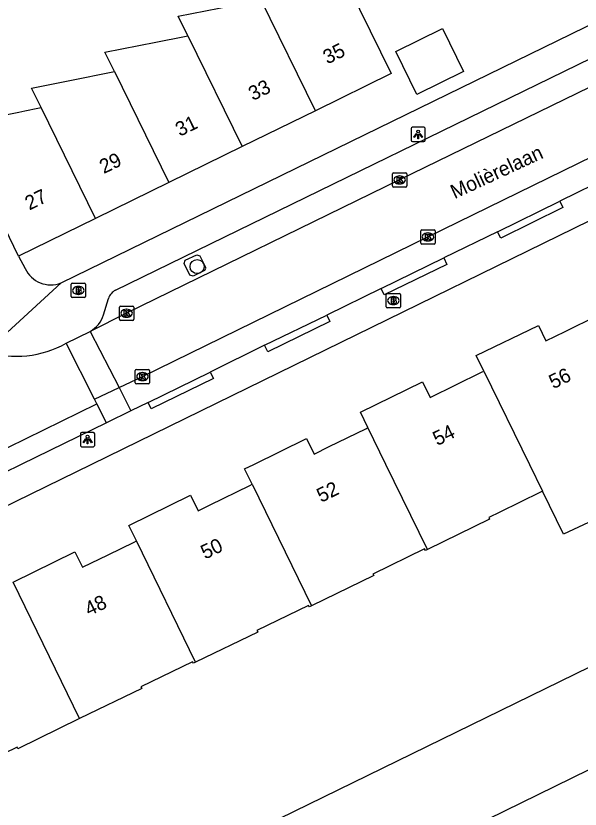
# Model space of a CAD drawing. Extents: x 160457 to 162082, y 388340 to 389736.
# Drawn here: x 160872.8 to 160912.2, y 388725.9 to 388781.3 of the extents above; entities that cross this region are included whole.
import ezdxf

# ---------------------------------------------------------------- set-up
doc = ezdxf.new("R2010")
doc.units = 0
for name, color, linetype in [('IMGEO_Boom', 7, 'Continuous'), ('IMGEO_Brandkraan', 7, 'Continuous'), ('IMGEO_Kolk', 7, 'Continuous'), ('IMGEO_Lichtpunt', 7, 'Continuous'), ('IMGEO_Openbare_ruimte_label', 7, 'Continuous'), ('IMGEO_Pand', 7, 'Continuous'), ('IMGEO_Pand_nummerreeks', 7, 'Continuous'), ('IMGEO_Parkeervlak_open', 7, 'Continuous'), ('IMGEO_Rijbaan_lokaal_gesloten', 7, 'Continuous'), ('IMGEO_Rijbaan_lokaal_open', 7, 'Continuous'), ('IMGEO_Voetpad_open', 7, 'Continuous'), ('IMGEO_Waterloop', 7, 'Continuous')]:
    doc.layers.add(name, color=color, linetype=linetype)

msp = doc.modelspace()

# ---------------------------------------------------------------- linework, layer by layer
at = {"layer": 'IMGEO_Boom'}
msp.add_circle((160885.427, 388763.797), 0.489, dxfattribs=at)
at = {"layer": 'IMGEO_Brandkraan'}
for p, q in [((160876.642, 388761.709), (160876.642, 388762.561)), ((160876.717, 388762.635), (160877.569, 388762.635)), ((160877.643, 388762.561), (160877.643, 388761.709)), ((160877.13, 388762.415), (160877.155, 388762.415)), ((160877.569, 388761.635), (160876.717, 388761.635)), ((160877.153, 388761.855), (160877.128, 388761.855)), ((160898.623, 388761.001), (160898.623, 388761.853)), ((160898.698, 388761.927), (160899.55, 388761.927)), ((160899.111, 388761.707), (160899.136, 388761.707)), ((160899.624, 388761.853), (160899.624, 388761.001)), ((160899.55, 388760.927), (160898.698, 388760.927)), ((160899.134, 388761.147), (160899.109, 388761.147))]:
    msp.add_line(p, q, dxfattribs=at)
for points in [[(160876.642, 388761.709), (160876.642, 388762.561)], [(160876.717, 388762.635), (160877.569, 388762.635)], [(160877.643, 388762.561), (160877.643, 388761.709)], [(160876.99, 388762.335), (160876.99, 388761.935), (160877.203, 388761.935)], [(160877.221, 388762.335), (160876.99, 388762.335)], [(160877.169, 388762.254), (160877.115, 388762.254), (160877.115, 388762.178)], [(160877.115, 388762.178), (160877.168, 388762.178)], [(160877.177, 388762.102), (160877.115, 388762.102), (160877.115, 388762.021)], [(160877.115, 388762.021), (160877.177, 388762.021)], [(160877.569, 388761.635), (160876.717, 388761.635)], [(160898.623, 388761.001), (160898.623, 388761.853)], [(160898.698, 388761.927), (160899.55, 388761.927)], [(160898.971, 388761.627), (160898.971, 388761.227), (160899.184, 388761.227)], [(160899.202, 388761.627), (160898.971, 388761.627)], [(160899.15, 388761.546), (160899.096, 388761.546), (160899.096, 388761.47)], [(160899.096, 388761.47), (160899.149, 388761.47)], [(160899.624, 388761.853), (160899.624, 388761.001)], [(160899.55, 388760.927), (160898.698, 388760.927)], [(160899.158, 388761.394), (160899.096, 388761.394), (160899.096, 388761.313)], [(160899.096, 388761.313), (160899.158, 388761.313)]]:
    msp.add_lwpolyline(points, dxfattribs=at)
for centre, radius, start, end in [((160876.719, 388762.559), 0.0765, 91.552, 178.448), ((160876.719, 388762.559), 0.0765, 91.552, 178.448), ((160877.567, 388762.559), 0.0765, 1.552, 88.448), ((160877.567, 388762.559), 0.0765, 1.552, 88.448), ((160877.17, 388762.216), 0.0379, 267.8285, 90.9355), ((160877.178, 388762.061), 0.0404, 269.8759, 90.5077), ((160877.225, 388762.19), 0.145, 59.4692, 91.5367), ((160877.25, 388762.237), 0.0922, 285.5137, 58.1501), ((160877.255, 388762.045), 0.105, 301.3115, 78.989), ((160876.719, 388761.711), 0.0765, 181.552, 268.448), ((160876.719, 388761.711), 0.0765, 181.552, 268.448), ((160877.209, 388762.186), 0.251, 268.6676, 293.5347), ((160877.567, 388761.711), 0.0765, 271.552, 358.448), ((160877.567, 388761.711), 0.0765, 271.552, 358.448), ((160898.7, 388761.851), 0.0765, 91.552, 178.448), ((160898.7, 388761.851), 0.0765, 91.552, 178.448), ((160899.151, 388761.508), 0.0379, 267.8285, 90.9355), ((160899.206, 388761.482), 0.145, 59.4692, 91.5367), ((160899.231, 388761.529), 0.0922, 285.5137, 58.1501), ((160899.236, 388761.337), 0.105, 301.3115, 78.989), ((160899.548, 388761.851), 0.0765, 1.552, 88.448), ((160899.548, 388761.851), 0.0765, 1.552, 88.448), ((160898.7, 388761.003), 0.0765, 181.552, 268.448), ((160898.7, 388761.003), 0.0765, 181.552, 268.448), ((160899.159, 388761.353), 0.0404, 269.8759, 90.5077), ((160899.19, 388761.478), 0.251, 268.6676, 293.5347), ((160899.548, 388761.003), 0.0765, 271.552, 358.448), ((160899.548, 388761.003), 0.0765, 271.552, 358.448)]:
    msp.add_arc(centre, radius, start, end, dxfattribs=at)
for centre, major_axis, ratio, start_param, end_param in [((160877.129, 388762.135), (-0.387, 0.002), 0.722429, 4.712389, 7.853982), ((160877.154, 388762.135), (-0.39, 0.002), 0.717154, 1.570796, 4.712389), ((160899.11, 388761.427), (-0.387, 0.002), 0.722429, 4.712389, 7.853982), ((160899.135, 388761.427), (-0.39, 0.002), 0.717154, 1.570796, 4.712389)]:
    msp.add_ellipse(centre, major_axis=major_axis, ratio=ratio, start_param=start_param, end_param=end_param, dxfattribs=at)
at = {"layer": 'IMGEO_Kolk'}
for p, q in [((160899.059, 388769.421), (160899.059, 388770.273)), ((160899.134, 388770.347), (160899.986, 388770.347)), ((160900.06, 388770.273), (160900.06, 388769.421)), ((160899.547, 388770.127), (160899.572, 388770.127)), ((160899.986, 388769.347), (160899.134, 388769.347)), ((160899.57, 388769.567), (160899.545, 388769.567)), ((160901.034, 388765.438), (160901.034, 388766.29)), ((160901.109, 388766.364), (160901.961, 388766.364)), ((160901.522, 388766.144), (160901.547, 388766.144)), ((160902.035, 388766.29), (160902.035, 388765.438)), ((160901.961, 388765.364), (160901.109, 388765.364)), ((160901.545, 388765.584), (160901.52, 388765.584)), ((160880.009, 388760.12), (160880.009, 388760.972)), ((160880.084, 388761.046), (160880.936, 388761.046)), ((160881.01, 388760.972), (160881.01, 388760.12)), ((160880.497, 388760.826), (160880.522, 388760.826)), ((160880.936, 388760.046), (160880.084, 388760.046)), ((160880.52, 388760.266), (160880.495, 388760.266)), ((160881.116, 388755.698), (160881.116, 388756.55)), ((160881.191, 388756.624), (160882.043, 388756.624)), ((160882.117, 388756.55), (160882.117, 388755.698)), ((160881.604, 388756.404), (160881.629, 388756.404)), ((160882.043, 388755.624), (160881.191, 388755.624)), ((160881.627, 388755.844), (160881.602, 388755.844))]:
    msp.add_line(p, q, dxfattribs=at)
for points in [[(160899.059, 388769.421), (160899.059, 388770.273)], [(160899.134, 388770.347), (160899.986, 388770.347)], [(160900.06, 388770.273), (160900.06, 388769.421)], [(160899.38, 388770.047), (160899.503, 388770.047), (160899.503, 388769.896), (160899.633, 388770.047), (160899.797, 388770.047), (160899.651, 388769.896), (160899.804, 388769.647), (160899.652, 388769.647), (160899.567, 388769.811), (160899.503, 388769.744), (160899.503, 388769.647), (160899.38, 388769.647), (160899.38, 388770.047)], [(160899.986, 388769.347), (160899.134, 388769.347)], [(160901.034, 388765.438), (160901.034, 388766.29)], [(160901.109, 388766.364), (160901.961, 388766.364)], [(160901.355, 388766.064), (160901.478, 388766.064), (160901.478, 388765.913), (160901.608, 388766.064), (160901.772, 388766.064), (160901.626, 388765.913), (160901.779, 388765.664), (160901.627, 388765.664), (160901.542, 388765.828), (160901.478, 388765.761), (160901.478, 388765.664), (160901.355, 388765.664), (160901.355, 388766.064)], [(160902.035, 388766.29), (160902.035, 388765.438)], [(160901.961, 388765.364), (160901.109, 388765.364)], [(160880.009, 388760.12), (160880.009, 388760.972)], [(160880.084, 388761.046), (160880.936, 388761.046)], [(160881.01, 388760.972), (160881.01, 388760.12)], [(160880.33, 388760.746), (160880.453, 388760.746), (160880.453, 388760.595), (160880.583, 388760.746), (160880.747, 388760.746), (160880.601, 388760.595), (160880.754, 388760.346), (160880.602, 388760.346), (160880.517, 388760.51), (160880.453, 388760.443), (160880.453, 388760.346), (160880.33, 388760.346), (160880.33, 388760.746)], [(160880.936, 388760.046), (160880.084, 388760.046)], [(160881.116, 388755.698), (160881.116, 388756.55)], [(160881.191, 388756.624), (160882.043, 388756.624)], [(160882.117, 388756.55), (160882.117, 388755.698)], [(160881.437, 388756.324), (160881.56, 388756.324), (160881.56, 388756.173), (160881.69, 388756.324), (160881.854, 388756.324), (160881.708, 388756.173), (160881.861, 388755.924), (160881.709, 388755.924), (160881.624, 388756.088), (160881.56, 388756.021), (160881.56, 388755.924), (160881.437, 388755.924), (160881.437, 388756.324)], [(160882.043, 388755.624), (160881.191, 388755.624)]]:
    msp.add_lwpolyline(points, dxfattribs=at)
for centre, start, end in [((160899.136, 388770.271), 91.552, 178.448), ((160899.136, 388770.271), 91.552, 178.448), ((160899.984, 388770.271), 1.552, 88.448), ((160899.984, 388770.271), 1.552, 88.448), ((160899.136, 388769.423), 181.552, 268.448), ((160899.136, 388769.423), 181.552, 268.448), ((160899.984, 388769.423), 271.552, 358.448), ((160899.984, 388769.423), 271.552, 358.448), ((160901.111, 388766.288), 91.552, 178.448), ((160901.111, 388766.288), 91.552, 178.448), ((160901.959, 388766.288), 1.552, 88.448), ((160901.959, 388766.288), 1.552, 88.448), ((160901.111, 388765.44), 181.552, 268.448), ((160901.111, 388765.44), 181.552, 268.448), ((160901.959, 388765.44), 271.552, 358.448), ((160901.959, 388765.44), 271.552, 358.448), ((160880.086, 388760.97), 91.552, 178.448), ((160880.086, 388760.97), 91.552, 178.448), ((160880.934, 388760.97), 1.552, 88.448), ((160880.934, 388760.97), 1.552, 88.448), ((160880.086, 388760.122), 181.552, 268.448), ((160880.086, 388760.122), 181.552, 268.448), ((160880.934, 388760.122), 271.552, 358.448), ((160880.934, 388760.122), 271.552, 358.448), ((160881.193, 388756.548), 91.552, 178.448), ((160881.193, 388756.548), 91.552, 178.448), ((160882.041, 388756.548), 1.552, 88.448), ((160882.041, 388756.548), 1.552, 88.448), ((160881.193, 388755.7), 181.552, 268.448), ((160881.193, 388755.7), 181.552, 268.448), ((160882.041, 388755.7), 271.552, 358.448), ((160882.041, 388755.7), 271.552, 358.448)]:
    msp.add_arc(centre, 0.0765, start, end, dxfattribs=at)
for centre, major_axis, ratio, start_param, end_param in [((160899.546, 388769.847), (-0.387, 0.002), 0.722429, 4.712389, 7.853982), ((160899.571, 388769.847), (-0.39, 0.002), 0.717154, 1.570796, 4.712389), ((160901.521, 388765.864), (-0.387, 0.002), 0.722429, 4.712389, 7.853982), ((160901.546, 388765.864), (-0.39, 0.002), 0.717154, 1.570796, 4.712389), ((160880.496, 388760.546), (-0.387, 0.002), 0.722429, 4.712389, 7.853982), ((160880.521, 388760.546), (-0.39, 0.002), 0.717154, 1.570796, 4.712389), ((160881.603, 388756.124), (-0.387, 0.002), 0.722429, 4.712389, 7.853982), ((160881.628, 388756.124), (-0.39, 0.002), 0.717154, 1.570796, 4.712389)]:
    msp.add_ellipse(centre, major_axis=major_axis, ratio=ratio, start_param=start_param, end_param=end_param, dxfattribs=at)
at = {"layer": 'IMGEO_Lichtpunt'}
for p, q in [((160900.355, 388773.421), (160900.355, 388772.614)), ((160900.355, 388773.421), (160900.355, 388772.614)), ((160901.257, 388773.516), (160900.449, 388773.516)), ((160901.257, 388773.516), (160900.449, 388773.516)), ((160901.351, 388772.614), (160901.351, 388773.421)), ((160901.351, 388772.614), (160901.351, 388773.421)), ((160900.449, 388772.52), (160901.257, 388772.52)), ((160900.449, 388772.52), (160901.257, 388772.52)), ((160877.289, 388752.135), (160877.289, 388751.328)), ((160877.289, 388752.135), (160877.289, 388751.328)), ((160878.191, 388752.23), (160877.383, 388752.23)), ((160878.191, 388752.23), (160877.383, 388752.23)), ((160878.285, 388751.328), (160878.285, 388752.135)), ((160878.285, 388751.328), (160878.285, 388752.135)), ((160877.383, 388751.234), (160878.191, 388751.234)), ((160877.383, 388751.234), (160878.191, 388751.234))]:
    msp.add_line(p, q, dxfattribs=at)
for points in [[(160900.729, 388773.085), (160900.768, 388773.057), (160900.58, 388772.795), (160900.542, 388772.822), (160900.729, 388773.085)], [(160900.831, 388773.037), (160900.878, 388773.037), (160900.878, 388772.715), (160900.831, 388772.715), (160900.831, 388773.037)], [(160900.941, 388773.057), (160900.979, 388773.084), (160901.166, 388772.822), (160901.127, 388772.794), (160900.941, 388773.057)], [(160877.663, 388751.799), (160877.702, 388751.771), (160877.514, 388751.509), (160877.476, 388751.536), (160877.663, 388751.799)], [(160877.765, 388751.751), (160877.812, 388751.751), (160877.812, 388751.429), (160877.765, 388751.429), (160877.765, 388751.751)], [(160877.875, 388751.771), (160877.913, 388751.798), (160878.1, 388751.536), (160878.061, 388751.508), (160877.875, 388751.771)]]:
    msp.add_lwpolyline(points, dxfattribs=at)
for centre in [(160900.854, 388773.219), (160877.788, 388751.933)]:
    msp.add_circle(centre, 0.0994, dxfattribs=at)
for centre, start, end in [((160900.449, 388773.421), 90, 180), ((160900.449, 388773.421), 90, 180), ((160901.257, 388773.421), 0, 90), ((160901.257, 388773.421), 0, 90), ((160900.449, 388772.614), 180, 270), ((160900.449, 388772.614), 180, 270), ((160901.257, 388772.614), 270, 0), ((160901.257, 388772.614), 270, 360), ((160877.383, 388752.135), 90, 180), ((160877.383, 388752.135), 90, 180), ((160878.191, 388752.135), 0, 90), ((160878.191, 388752.135), 0, 90), ((160877.383, 388751.328), 180, 270), ((160877.383, 388751.328), 180, 270), ((160878.191, 388751.328), 270, 0), ((160878.191, 388751.328), 270, 360)]:
    msp.add_arc(centre, 0.0946, start, end, dxfattribs=at)
at = {"layer": 'IMGEO_Pand'}
for points in [[(160889.897, 388782.413), (160889.234, 388783.768), (160889.07, 388784.103), (160894.367, 388786.694), (160895.228, 388784.923), (160896.769, 388781.756), (160898.969, 388777.266), (160893.681, 388774.675)], [(160884.78, 388779.906), (160884.117, 388781.262), (160887.932, 388782.021), (160889.672, 388782.368), (160889.897, 388782.413)], [(160893.681, 388774.675), (160889.897, 388782.413)], [(160899.294, 388778.812), (160902.551, 388780.407), (160904.026, 388777.398), (160900.769, 388775.802), (160899.294, 388778.812)], [(160879.663, 388777.399), (160879, 388778.755), (160882.554, 388779.462), (160884.555, 388779.861), (160884.78, 388779.906)], [(160884.78, 388779.906), (160888.563, 388772.168)], [(160874.546, 388774.892), (160873.883, 388776.248), (160876.661, 388776.801), (160879.438, 388777.354), (160879.663, 388777.399)], [(160879.663, 388777.399), (160883.446, 388769.66)], [(160868.516, 388773.685), (160872.989, 388774.58), (160873.419, 388774.666), (160874.321, 388774.847), (160874.546, 388774.892)], [(160878.329, 388767.153), (160874.546, 388774.892)], [(160893.681, 388774.675), (160888.563, 388772.168)], [(160872.977, 388764.531), (160868.516, 388773.685)], [(160888.563, 388772.168), (160883.446, 388769.66)], [(160883.446, 388769.66), (160878.329, 388767.153)], [(160878.329, 388767.153), (160872.977, 388764.531)], [(160905.432, 388756.511), (160904.905, 388757.589), (160909.244, 388759.7), (160909.769, 388758.621), (160911.113, 388759.28), (160913.365, 388760.383), (160913.506, 388760.452)], [(160897.351, 388752.562), (160896.824, 388753.641), (160901.153, 388755.751), (160901.679, 388754.672), (160903.479, 388755.554), (160905.278, 388756.436), (160905.432, 388756.511)], [(160905.432, 388756.511), (160908.615, 388750), (160909.532, 388748.124)], [(160889.269, 388748.608), (160888.742, 388749.687), (160889.385, 388750), (160893.068, 388751.796), (160893.594, 388750.717), (160894.654, 388751.238), (160897.195, 388752.486), (160897.351, 388752.562)], [(160901.5, 388744.065), (160898.602, 388750), (160897.351, 388752.562)], [(160917.66, 388751.963), (160917.512, 388751.891), (160917.46, 388751.998), (160916.111, 388751.339), (160916.803, 388750), (160917.703, 388748.259), (160910.996, 388745.13), (160909.532, 388748.124)], [(160881.194, 388744.662), (160880.669, 388745.741), (160884.978, 388747.842), (160885.505, 388746.764), (160886.34, 388747.173), (160889.113, 388748.532), (160889.269, 388748.608)], [(160889.269, 388748.608), (160893.408, 388740.129)], [(160909.532, 388748.124), (160909.385, 388748.052), (160906.545, 388746.665), (160905.775, 388746.288), (160905.828, 388746.18), (160901.5, 388744.065)], [(160872.599, 388741.787), (160876.898, 388743.896), (160877.427, 388742.819), (160879.228, 388743.7), (160881.029, 388744.581), (160881.194, 388744.662)], [(160885.316, 388736.194), (160881.194, 388744.662)], [(160901.5, 388744.065), (160901.355, 388743.994), (160901.303, 388744.102), (160897.696, 388742.348), (160897.749, 388742.24), (160893.408, 388740.129)], [(160877.233, 388732.263), (160872.599, 388741.787)], [(160893.408, 388740.129), (160893.261, 388740.058), (160893.209, 388740.166), (160889.603, 388738.412), (160889.655, 388738.304), (160885.316, 388736.194)], [(160885.316, 388736.194), (160885.168, 388736.122), (160885.115, 388736.23), (160881.509, 388734.476), (160881.562, 388734.368), (160877.233, 388732.263)], [(160877.233, 388732.263), (160872.919, 388730.166), (160872.867, 388730.274), (160869.261, 388728.52), (160869.313, 388728.412), (160869.159, 388728.337)]]:
    msp.add_lwpolyline(points, dxfattribs=at)
at = {"layer": 'IMGEO_Parkeervlak_open'}
for points in [[(160879.999, 388755.357), (160880.802, 388753.74)], [(160879.107, 388752.907), (160878.433, 388754.232)]]:
    msp.add_lwpolyline(points, dxfattribs=at)
at = {"layer": 'IMGEO_Rijbaan_lokaal_gesloten'}
for points in [[(160922.077, 388780.78), (160918.996, 388779.324), (160899.56, 388769.847), (160880.511, 388760.545), (160877.968, 388759.28)], [(160879.999, 388755.357), (160881.617, 388756.126), (160901.535, 388765.865), (160926.684, 388778.165), (160927.363, 388778.614), (160928.626, 388779.448)]]:
    msp.add_lwpolyline(points, dxfattribs=at)
at = {"layer": 'IMGEO_Rijbaan_lokaal_open'}
for points in [[(160876.286, 388758.451), (160877.968, 388759.28)], [(160877.968, 388759.28), (160879.999, 388755.357)], [(160878.277, 388754.538), (160876.286, 388758.451)], [(160878.277, 388754.538), (160879.999, 388755.357)], [(160860.175, 388745.303), (160869.779, 388750), (160878.433, 388754.232)], [(160878.433, 388754.232), (160878.277, 388754.538)]]:
    msp.add_lwpolyline(points, dxfattribs=at)
msp.add_arc((160872.838, 388764.541), 6.998, 252.3018, 299.5161, dxfattribs=at)
at = {"layer": 'IMGEO_Voetpad_open'}
for points in [[(160875.947, 388762.656), (160922.127, 388785.223)], [(160879.737, 388762.15), (160918.637, 388781.134)], [(160929.117, 388774.962), (160878.066, 388750), (160811.085, 388717.249)], [(160914.255, 388770.086), (160910.736, 388768.366)], [(160910.736, 388768.366), (160910.956, 388767.918), (160906.617, 388765.786), (160906.397, 388766.234)], [(160906.397, 388766.234), (160910.736, 388768.366)], [(160906.397, 388766.234), (160902.641, 388764.4)], [(160872.977, 388764.531), (160873.431, 388763.666)], [(160885.938, 388763.517), (160885.146, 388763.123), (160884.92, 388763.211), (160884.53, 388764.012), (160884.59, 388764.237), (160885.403, 388764.625), (160885.625, 388764.551), (160886.012, 388763.755)], [(160902.641, 388764.4), (160902.859, 388763.951), (160898.491, 388761.827), (160898.273, 388762.276)], [(160898.273, 388762.276), (160902.641, 388764.4)], [(160875.947, 388762.656), (160870.711, 388757.874)], [(160898.273, 388762.276), (160894.483, 388760.414)], [(160878.906, 388760.432), (160879.241, 388761.568)], [(160894.483, 388760.414), (160894.701, 388759.965), (160890.355, 388757.858), (160890.137, 388758.307)], [(160890.137, 388758.307), (160894.483, 388760.414)], [(160890.137, 388758.307), (160886.347, 388756.438)], [(160886.347, 388756.438), (160886.566, 388755.989), (160882.228, 388753.868), (160882.009, 388754.317)], [(160882.009, 388754.317), (160886.347, 388756.438)], [(160882.009, 388754.317), (160880.802, 388753.74)], [(160880.802, 388753.74), (160879.107, 388752.907)], [(160879.107, 388752.907), (160873.165, 388750), (160860.806, 388743.953)]]:
    msp.add_lwpolyline(points, dxfattribs=at)
for centre, radius, start, end in [((160875.231, 388764.512), 1.989, 205.1625, 291.0934), ((160885.855, 388763.673), 0.177, 298.0228, 27.4337), ((160880.179, 388761.271), 0.984, 116.6912, 162.4312), ((160876.995, 388761.03), 2.002, 299.0667, 342.6259)]:
    msp.add_arc(centre, radius, start, end, dxfattribs=at)
at = {"layer": 'IMGEO_Waterloop'}
for points in [[(161004.045, 388773.679), (161000, 388771.638), (160986.989, 388765.073), (160956.23, 388750), (160783.435, 388665.323), (160769.08, 388658.493)], [(160766.298, 388664.267), (160941.708, 388750), (160948.921, 388753.525)]]:
    msp.add_lwpolyline(points, dxfattribs=at)

# ---------------------------------------------------------------- texts
at = {"layer": 'IMGEO_Openbare_ruimte_label'}
msp.add_text('Molièrelaan', height=1, rotation=24.8992, dxfattribs=at).set_placement((160903.398, 388768.493))
at = {"layer": 'IMGEO_Pand_nummerreeks'}
for s, rotation, p in [('35', 26.104, (160894.519, 388777.892)), ('33', 26.104, (160889.32, 388775.345)), ('31', 26.104, (160884.224, 388772.848)), ('29', 26.104, (160878.924, 388770.251)), ('27', 26.104, (160873.725, 388767.704)), ('56', 26.0696, (160910.281, 388755.237)), ('54', 26.0696, (160902.183, 388751.275)), ('52', 26.0696, (160894.082, 388747.312)), ('50', 26.0696, (160885.99, 388743.353)), ('48', 26.0696, (160877.892, 388739.391))]:
    msp.add_text(s, height=1, rotation=rotation, dxfattribs=at).set_placement(p)

doc.saveas('drawing.dxf')
